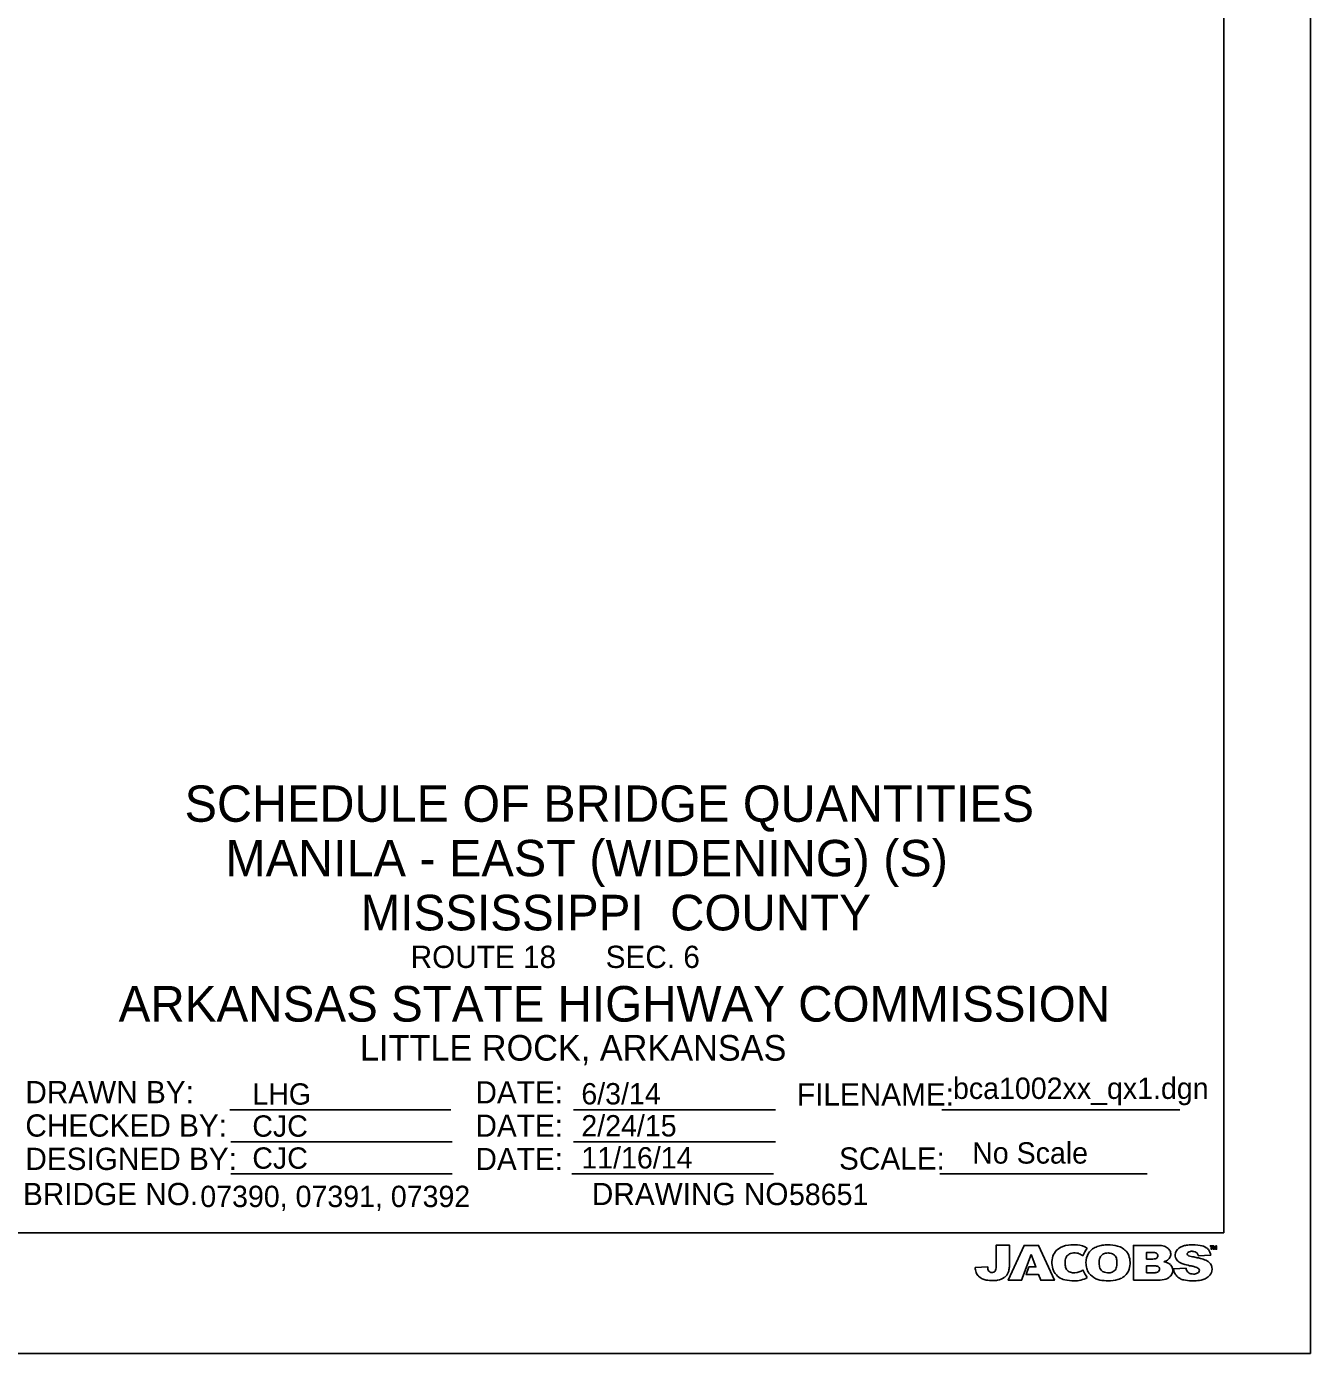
# Model space of a CAD drawing. Extents: x 117751.5 to 117785.6, y 28052.1 to 28074.
# Drawn here: x 117778.43 to 117785.65, y 28052.15 to 28059.6 of the extents above; entities that cross this region are included whole.
import ezdxf

# ---------------------------------------------------------------- set-up
doc = ezdxf.new("R2010")
doc.units = 0
for name, color, linetype in [('border', 7, 'Continuous'), ('Level 1', 7, 'Continuous'), ('Level 2', 7, 'Continuous'), ('Level 62', 7, 'Continuous'), ('Text', 7, 'Continuous'), ('Title Text', 7, 'Continuous')]:
    doc.layers.add(name, color=color, linetype=linetype)

msp = doc.modelspace()

# ---------------------------------------------------------------- linework, layer by layer
at = {"layer": 'border'}
for p, q in [((117785.1609, 28052.8257), (117785.1609, 28073.3709)), ((117779.5737, 28053.5169), (117780.8169, 28053.5169)), ((117781.5069, 28053.5158), (117782.6409, 28053.5158)), ((117783.5769, 28053.5158), (117784.913, 28053.5158)), ((117779.5809, 28053.3369), (117780.8241, 28053.3369)), ((117781.5069, 28053.3358), (117782.6409, 28053.3358)), ((117779.5809, 28053.1569), (117780.8241, 28053.1569)), ((117781.4961, 28053.1558), (117782.6301, 28053.1558)), ((117783.5645, 28053.1558), (117784.7301, 28053.1558)), ((117785.1609, 28052.8257), (117753.1497, 28052.8257))]:
    msp.add_line(p, q, dxfattribs=at)
for points in [[(117783.9557, 28052.6461), (117783.9557, 28052.7562), (117783.8816, 28052.7562), (117783.8816, 28052.6355)], [(117784.0785, 28052.7036), (117784.1046, 28052.6331), (117784.0658, 28052.6331), (117784.0498, 28052.5908), (117784.12, 28052.5908), (117784.1318, 28052.5584), (117784.2092, 28052.5584), (117784.1197, 28052.7544), (117784.0389, 28052.7544), (117783.9491, 28052.5584), (117784.0247, 28052.5584), (117784.0785, 28052.7036)], [(117784.7949, 28052.7544), (117784.6527, 28052.7544), (117784.6527, 28052.5584)], [(117785.0995, 28052.752), (117785.0844, 28052.752), (117785.0844, 28052.7502), (117785.0904, 28052.7502), (117785.0904, 28052.7332), (117785.0931, 28052.7332), (117785.0931, 28052.7502), (117785.0995, 28052.7502), (117785.0995, 28052.752)], [(117785.104, 28052.749), (117785.104, 28052.749), (117785.1101, 28052.7332), (117785.1119, 28052.7332), (117785.1179, 28052.749), (117785.1179, 28052.749), (117785.1179, 28052.7332), (117785.1204, 28052.7332), (117785.1204, 28052.752), (117785.117, 28052.752), (117785.111, 28052.7363), (117785.1049, 28052.752), (117785.1016, 28052.752), (117785.1016, 28052.7332), (117785.104, 28052.7332), (117785.104, 28052.749)], [(117784.7598, 28052.7148), (117784.7271, 28052.7148), (117784.7271, 28052.6776)], [(117784.7271, 28052.6776), (117784.7616, 28052.6776)], [(117785.0178, 28052.696), (117785.0877, 28052.6994)], [(117783.8341, 28052.6346), (117783.7633, 28052.631)], [(117784.7646, 28052.6401), (117784.7271, 28052.6401), (117784.7271, 28052.6004)], [(117784.7271, 28052.6004), (117784.7652, 28052.6004)], [(117784.9488, 28052.6268), (117784.8787, 28052.6231)], [(117784.6527, 28052.5584), (117784.7803, 28052.5584)]]:
    msp.add_lwpolyline(points, dxfattribs=at)
for centre, radius, start, end in [((117784.2777, 28052.669), 0.0809, 126.85134, 155.24445), ((117784.2974, 28052.6428), 0.1137, 94.78534, 126.85134), ((117784.3182, 28052.3944), 0.3629, 86.90301, 94.78534), ((117784.3317, 28052.6443), 0.1126, 56.9246, 86.90301), ((117784.618, 28052.5791), 0.2758, 144.63502, 154.88444), ((117784.4655, 28052.6717), 0.0755, 123.8806, 148.62486), ((117784.5026, 28052.6164), 0.1421, 111.71043, 123.8806), ((117784.4905, 28052.6468), 0.1094, 96.53712, 111.71043), ((117784.5218, 28052.3742), 0.3838, 91.9058, 96.53711), ((117784.516, 28052.5918), 0.1661, 73.44767, 92.42532), ((117784.5314, 28052.6436), 0.1121, 41.1934, 73.44767), ((117784.7949, 28052.6507), 0.1036, 72.18854, 90.1477), ((117784.8082, 28052.692), 0.0603, 61.48438, 72.18854), ((117784.81, 28052.6954), 0.0564, 34.7868, 61.48438), ((117784.9351, 28052.6993), 0.0476, 124.07995, 177.64848), ((117784.9663, 28052.6533), 0.1032, 108.28083, 124.07995), ((117784.9593, 28052.6743), 0.0811, 99.81734, 108.28082), ((117784.9868, 28052.5153), 0.2425, 93.402, 99.81734), ((117784.9875, 28052.5039), 0.2539, 80.65488, 93.40199), ((117785.0142, 28052.6659), 0.0897, 57.59056, 80.65488), ((117785.0358, 28052.7), 0.0494, 39.0736, 57.59056), ((117784.3483, 28052.6603), 0.1532, 178.6811, 194.39118), ((117784.2939, 28052.6615), 0.0987, 155.24445, 178.6811), ((117784.3724, 28052.6539), 0.1037, 161.28337, 178.67021), ((117784.2972, 28052.6794), 0.0243, 134.3139, 161.28337), ((117784.3191, 28052.6569), 0.0556, 110.76549, 134.31389), ((117784.3181, 28052.6594), 0.0529, 91.50728, 110.76549), ((117784.3198, 28052.5965), 0.1159, 82.6359, 91.50728), ((117784.3283, 28052.6626), 0.0493, 65.55483, 82.6359), ((117784.2996, 28052.5994), 0.1187, 54.60016, 65.55482), ((117784.4867, 28052.6588), 0.1003, 148.62486, 181.28594), ((117784.5519, 28052.6562), 0.0917, 160.86113, 181.29811), ((117784.4924, 28052.6768), 0.0287, 136.11771, 160.86113), ((117784.5091, 28052.6608), 0.0518, 117.7176, 136.11771), ((117784.5028, 28052.6728), 0.0382, 100.21085, 117.7176), ((117784.5118, 28052.6224), 0.0895, 90.96753, 100.21085), ((117784.5108, 28052.6497), 0.0622, 67.07702, 90.42176), ((117784.52, 28052.6714), 0.0386, 24.62738, 67.07702), ((117784.5042, 28052.6641), 0.056, 2.74416, 24.62738), ((117784.311, 28052.6549), 0.2494, 0.08449, 2.74416), ((117784.5722, 28052.6793), 0.0579, 18.69658, 41.1934), ((117784.5035, 28052.656), 0.1305, 344.57078, 18.69658), ((117784.7583, 28052.5796), 0.1352, 86.2098, 89.3498), ((117784.7615, 28052.7409), 0.0633, 270.03631, 284.14376), ((117784.7638, 28052.6631), 0.0514, 74.87225, 86.2098), ((117784.7722, 28052.6986), 0.0196, 284.14376, 307.88655), ((117784.7721, 28052.6939), 0.0196, 40.24248, 74.87225), ((117784.7751, 28052.6949), 0.0149, 307.88655, 341.46246), ((117784.7788, 28052.6996), 0.0108, 21.96041, 40.24248), ((117784.7708, 28052.6963), 0.0195, 341.46246, 21.96041), ((117784.8046, 28052.7356), 0.0753, 284.67851, 296.84115), ((117784.8076, 28052.5722), 0.092, 61.0815, 79.92424), ((117784.8174, 28052.7104), 0.0471, 296.84115, 329.81819), ((117784.8305, 28052.7096), 0.0315, 16.94547, 34.7868), ((117784.8315, 28052.7022), 0.0307, 329.81819, 347.09492), ((117784.8171, 28052.7055), 0.0455, 347.09493, 16.94546), ((117784.9291, 28052.6996), 0.0416, 177.64848, 218.85347), ((117784.9408, 28052.709), 0.0566, 218.85347, 233.65492), ((117784.9545, 28052.7275), 0.0797, 233.65493, 244.76888), ((117784.9638, 28052.7062), 0.00815, 165.3108, 208.28871), ((117784.9713, 28052.7042), 0.016, 146.47062, 165.31079), ((117784.971, 28052.7112), 0.0169, 211.74165, 226.63389), ((117784.9653, 28052.7081), 0.00877, 130.78548, 146.47062), ((117784.9693, 28052.7094), 0.0145, 226.63389, 245.14291), ((117784.9763, 28052.6954), 0.0256, 97.30547, 130.78548), ((117784.9863, 28052.7461), 0.0549, 245.14291, 260.98065), ((117784.9819, 28052.6521), 0.0692, 81.32121, 97.30546), ((117784.9025, 28052.2184), 0.4794, 77.5139, 80.98065), ((117784.9869, 28052.6851), 0.0359, 57.47403, 81.32121), ((117784.9953, 28052.6983), 0.0202, 37.19775, 57.47403), ((117784.5787, 28050.756), 1.9772, 76.80348, 77.5139), ((117784.9835, 28052.6893), 0.0351, 11.00509, 37.19775), ((117784.9928, 28052.5222), 0.1631, 65.69981, 76.80348), ((117785.028, 28052.6001), 0.0776, 51.35648, 65.6998), ((117785.0266, 28052.6925), 0.0612, 6.43854, 39.0736), ((117785.0438, 28052.6199), 0.0523, 36.51625, 51.35648), ((117783.8853, 28052.6406), 0.1226, 184.56975, 198.10689), ((117783.8188, 28052.6188), 0.0527, 198.1069, 225.97986), ((117783.8945, 28052.6326), 0.0602, 178.25555, 191.49609), ((117783.8626, 28052.6261), 0.0277, 191.49609, 218.75114), ((117783.8538, 28052.619), 0.0164, 218.75114, 257.48803), ((117783.8577, 28052.6367), 0.0345, 257.48804, 275.78339), ((117783.8586, 28052.628), 0.0257, 275.78339, 301.69258), ((117783.8657, 28052.6165), 0.0122, 301.69258, 325.41713), ((117783.8523, 28052.6257), 0.0285, 325.41713, 349.15753), ((117783.8025, 28052.6353), 0.0792, 349.15753, 360), ((117783.8951, 28052.6226), 0.0585, 305.86462, 338.78432), ((117783.9005, 28052.6205), 0.0527, 338.78433, 350.09512), ((117783.4115, 28052.7059), 0.5492, 350.09512, 351.37058), ((117783.8321, 28052.6421), 0.1237, 351.37058, 1.82911), ((117784.2563, 28052.6367), 0.0582, 194.39118, 214.17986), ((117784.3131, 28052.6752), 0.1268, 214.17986, 231.66155), ((117784.3541, 28052.6543), 0.0855, 178.67021, 195.85307), ((117784.3124, 28052.6424), 0.0421, 195.85308, 214.53695), ((117784.3097, 28052.6406), 0.0388, 214.53695, 253.19175), ((117784.3207, 28052.677), 0.0769, 253.19175, 291.19559), ((117784.315, 28052.6919), 0.0928, 291.19559, 305.51438), ((117784.7321, 28052.7992), 0.4066, 206.7197, 213.67795), ((117784.5387, 28052.66), 0.1523, 181.28594, 193.19556), ((117784.4569, 28052.6408), 0.0683, 193.19556, 217.74992), ((117784.4906, 28052.6669), 0.1109, 217.74992, 244.17034), ((117784.5553, 28052.6563), 0.0951, 181.29811, 197.94918), ((117784.4933, 28052.6362), 0.0299, 197.94918, 222.77411), ((117784.5061, 28052.648), 0.0474, 222.77411, 250.19554), ((117784.5072, 28052.6511), 0.0507, 250.19554, 269.12639), ((117784.5094, 28052.7915), 0.1911, 269.12639, 272.0424), ((117784.5144, 28052.6517), 0.0512, 272.0424, 299.54008), ((117784.5219, 28052.6385), 0.036, 299.54008, 342.40029), ((117784.4694, 28052.6551), 0.091, 342.40029, 0.08449), ((117784.5375, 28052.6585), 0.1005, 285.90169, 322.67136), ((117784.562, 28052.6399), 0.0698, 322.67136, 344.57078), ((117784.7599, 28052.3932), 0.2471, 86.68376, 88.87562), ((117784.765, 28052.7044), 0.104, 270.00009, 276.67494), ((117784.7713, 28052.5903), 0.0497, 75.93141, 86.68375), ((117784.7721, 28052.6439), 0.043, 276.67494, 293.06453), ((117784.7754, 28052.6067), 0.0328, 59.62021, 75.9314), ((117784.7819, 28052.6207), 0.0178, 293.06453, 337.5037), ((117784.7844, 28052.622), 0.015, 30.83409, 59.62021), ((117784.7821, 28052.6207), 0.0177, 337.50371, 30.83409), ((117784.8333, 28052.6186), 0.039, 44.97734, 61.0815), ((117784.8232, 28052.6159), 0.0511, 313.6357, 342.98447), ((117784.8289, 28052.6142), 0.0452, 342.98447, 44.97734), ((117785.2547, 28052.6761), 0.3799, 187.9971, 189.09474), ((117784.9292, 28052.624), 0.0503, 189.09474, 202.46404), ((117784.9641, 28052.6384), 0.0881, 202.46404, 215.89258), ((117784.9431, 28052.6232), 0.0621, 215.89258, 243.29677), ((117784.9871, 28052.7968), 0.1563, 244.76888, 253.47301), ((117785.0346, 28052.9571), 0.3234, 253.47301, 259.82965), ((117785.0005, 28052.6346), 0.0523, 188.51407, 201.638), ((117784.9815, 28052.627), 0.0319, 201.638, 242.36347), ((117784.9876, 28052.6386), 0.045, 242.36347, 264.62285), ((117784.9252, 28052.3468), 0.2966, 76.01042, 79.82965), ((117784.9909, 28052.6741), 0.0806, 264.62285, 273.90099), ((117784.9932, 28052.6399), 0.0464, 273.901, 289.19251), ((117784.9733, 28052.5401), 0.0974, 67.95933, 76.01043), ((117784.9998, 28052.621), 0.0263, 289.19251, 322.56596), ((117784.9999, 28052.6058), 0.0265, 39.93128, 67.95933), ((117785.0092, 28052.6135), 0.0145, 2.18131, 39.93128), ((117785.0096, 28052.6135), 0.0141, 322.56597, 2.18131), ((117785.035, 28052.6252), 0.0608, 314.02195, 345.16113), ((117785.0468, 28052.6221), 0.0486, 345.16113, 36.51625), ((117783.8376, 28052.6383), 0.0797, 225.97986, 261.07142), ((117783.8631, 28052.8007), 0.2441, 261.07143, 269.94051), ((117783.8631, 28052.7237), 0.1671, 269.94051, 279.1616), ((117783.8748, 28052.6507), 0.0931, 279.1616, 305.86462), ((117784.2819, 28052.6358), 0.0765, 231.66155, 258.68595), ((117784.3253, 28052.8529), 0.298, 258.68595, 268.81632), ((117784.3222, 28052.7007), 0.1457, 268.81632, 299.38782), ((117784.4797, 28052.6444), 0.0859, 244.17034, 259.49425), ((117784.5186, 28052.8542), 0.2993, 259.49425, 268.64264), ((117784.5158, 28052.7349), 0.1799, 268.64264, 285.90168), ((117784.7701, 28052.8963), 0.3381, 271.72242, 279.62791), ((117784.8164, 28052.6231), 0.0609, 279.62791, 313.6357), ((117784.9559, 28052.6485), 0.0904, 243.29677, 257.45982), ((117784.9824, 28052.768), 0.2128, 257.45982, 268.86561), ((117784.9897, 28053.1362), 0.5811, 268.86561, 270.76117), ((117784.9951, 28052.7325), 0.1774, 270.76117, 282.50008), ((117785.0099, 28052.6657), 0.109, 282.50008, 295.61438), ((117785.0236, 28052.637), 0.0772, 295.61437, 314.02195)]:
    msp.add_arc(centre, radius, start, end, dxfattribs=at)
at = {"layer": 'Level 62'}
msp.add_lwpolyline([(117751.5296, 28073.9567), (117785.6481, 28073.9567), (117785.6481, 28052.1471), (117751.5296, 28052.1471)], close=True, dxfattribs=at)

# ---------------------------------------------------------------- texts
at = {"layer": 'Level 1'}
msp.add_text('bca1002xx_qx1.dgn', height=0.12, dxfattribs=at).set_placement((117783.639, 28053.5776))
at = {"layer": 'Level 2'}
for s, height, p in [('SCHEDULE OF BRIDGE QUANTITIES', 0.203998, (117779.3201, 28055.1354)), ('MANILA - EAST (WIDENING) (S)', 0.203998, (117779.5487, 28054.8294)), ('LHG', 0.12, (117779.7009, 28053.5453)), ('6/3/14', 0.12, (117781.5501, 28053.5467)), ('CJC', 0.12, (117779.7009, 28053.3653)), ('2/24/15', 0.12, (117781.5501, 28053.3667)), ('No Scale', 0.12, (117783.7468, 28053.2141)), ('CJC', 0.12, (117779.7009, 28053.1853)), ('11/16/14', 0.12, (117781.5501, 28053.1867)), ('07390, 07391, 07392', 0.120002, (117779.4085, 28052.9698)), ('58651', 0.12, (117782.7169, 28052.9812))]:
    msp.add_text(s, height=height, dxfattribs=at).set_placement(p)
at = {"layer": 'Text'}
for s, p in [('DRAWN BY:', (117778.4253, 28053.5534)), ('DATE:', (117780.9549, 28053.5524)), ('FILENAME:', (117782.7619, 28053.5403)), ('CHECKED BY:', (117778.4253, 28053.3659)), ('DATE:', (117780.9549, 28053.3649)), ('DESIGNED BY:', (117778.4253, 28053.1784)), ('DATE:', (117780.9549, 28053.1774)), ('SCALE:', (117782.9985, 28053.1803)), ('BRIDGE NO.', (117778.4118, 28052.9808)), ('DRAWING NO.', (117781.6092, 28052.981))]:
    msp.add_text(s, height=0.125, dxfattribs=at).set_placement(p)
at = {"layer": 'Title Text'}
for s, height, p in [('MISSISSIPPI  COUNTY', 0.2, (117780.3099, 28054.5248)), ('ROUTE 18      SEC. 6', 0.125, (117780.5907, 28054.3137)), ('ARKANSAS STATE HIGHWAY COMMISSION', 0.2, (117778.9495, 28054.0122)), ('LITTLE ROCK, ARKANSAS', 0.144, (117780.3057, 28053.7929))]:
    msp.add_text(s, height=height, dxfattribs=at).set_placement(p)

doc.saveas('drawing.dxf')
